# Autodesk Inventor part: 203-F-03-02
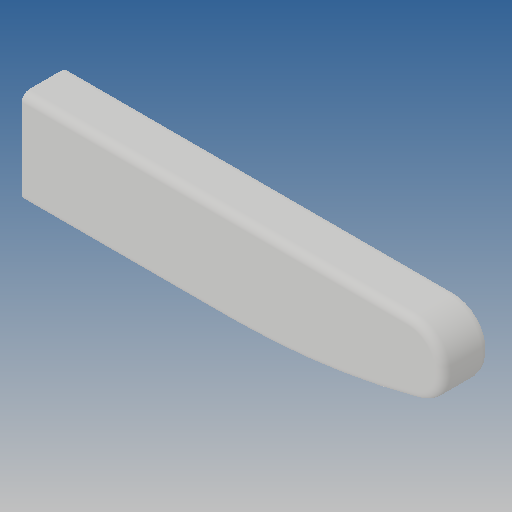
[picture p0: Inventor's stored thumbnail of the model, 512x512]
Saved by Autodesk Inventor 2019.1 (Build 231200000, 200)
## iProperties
Created: 2012-09
Part Number: 203-F-03-02
Material: Ogólny
Document SubType Name: Modeling
Designer: CADENGINEERING4
Density: 1 g/cm^3
Appearance: Domyślna
Author: CADENGINEERING4
Revision Number: ÈÎºÎ
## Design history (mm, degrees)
feature "³é¿Ç2"
node "Bryła1"
